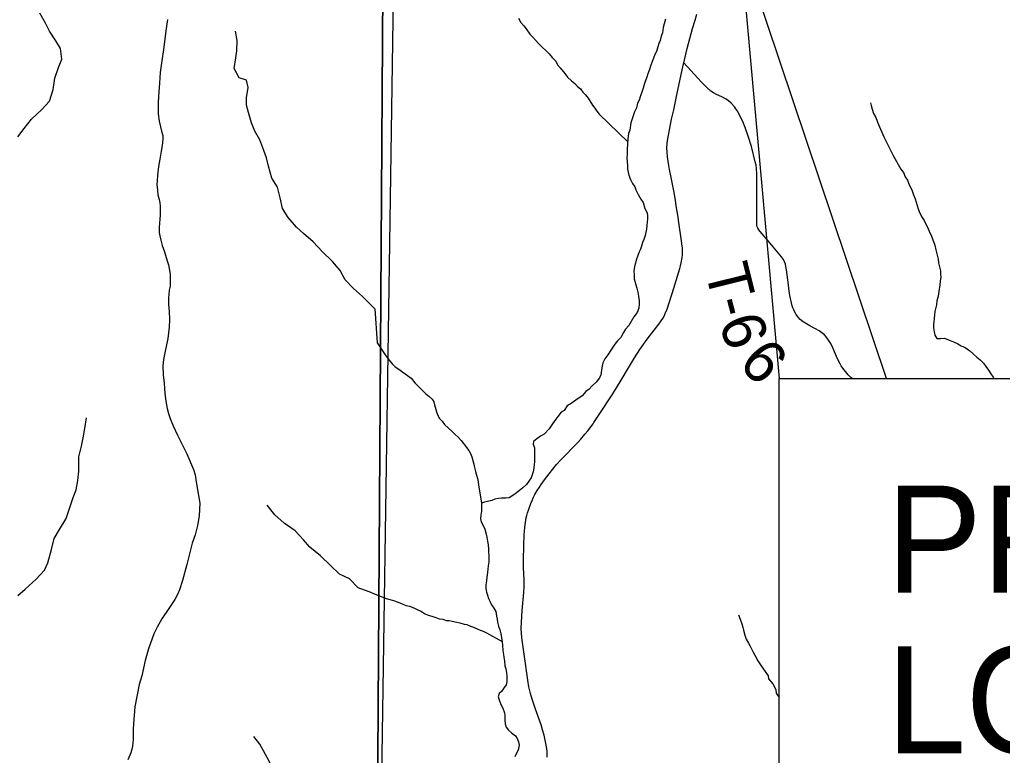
# Model space of a CAD drawing. Extents: x 0 to 34, y 0 to 22.
# Drawn here: x 26.547 to 27.832, y 15.526 to 16.488 of the extents above; entities that cross this region are included whole.
import ezdxf

# ---------------------------------------------------------------- set-up
doc = ezdxf.new("R2010")
doc.units = 0
for name, color, linetype in [('GM_X_Corporation', 7, 'Continuous'), ('GM_X_County', 7, 'Continuous'), ('GM_X_Minor_River', 7, 'Continuous'), ('GM_X_State_Route', 7, 'Continuous'), ('GM_X_Township_Road', 7, 'Continuous'), ('GM_X_Township_Road_Text', 7, 'Continuous'), ('SH_Data', 7, 'Continuous'), ('SH_Text', 7, 'Continuous')]:
    doc.layers.add(name, color=color, linetype=linetype)

msp = doc.modelspace()

# ---------------------------------------------------------------- linework, layer by layer
at = {"layer": 'GM_X_Corporation'}
for points in [[(30.3167, 20.9), (27.1022, 20.9), (27.0898, 20.417), (27.0897, 20.4135), (27.089, 20.3692), (27.0873, 20.2665), (27.0907, 20.123), (27.0885, 20.1139), (27.0864, 20.0138), (27.0761, 19.6806), (27.0733, 19.498), (27.0719, 19.3912), (27.0487, 18.5805), (27.0419, 17.8236), (27.0349, 17.5522), (27.0234, 16.6611), (27.0124, 14.988), (27.0057, 14.5136), (27.2999, 14.5107), (27.8031, 14.5091), (28.4032, 14.497)], [(29.5503, 20.3788), (27.6751, 20.4106), (27.5829, 20.4116), (27.2336, 20.4152), (27.1239, 20.4163), (27.0898, 20.417), (27.0897, 20.4135), (27.089, 20.3692), (27.0873, 20.2665), (27.0907, 20.123), (27.0885, 20.1139), (27.0864, 20.0138), (27.0761, 19.6806), (27.0733, 19.498), (27.0719, 19.3912), (27.0487, 18.5805), (27.0419, 17.8236), (27.0349, 17.5522), (27.0234, 16.6611), (27.0124, 14.988), (27.0057, 14.5136), (27.2999, 14.5107), (27.8031, 14.5091), (28.4032, 14.497)], [(23.5167, 20.3276), (23.5167, 14.5642), (23.7464, 14.562), (24.4108, 14.5557), (24.414, 14.5556), (24.9788, 14.5503), (25.0494, 14.5496), (25.56, 14.5392), (26.009, 14.53), (26.3333, 14.5233), (26.7998, 14.5186), (27.0057, 14.5136), (27.0124, 14.988), (27.0234, 16.6611), (27.0349, 17.5522)], [(23.5167, 20.3276), (23.5167, 14.5642), (23.7464, 14.562), (24.4108, 14.5557), (24.414, 14.5556), (24.9788, 14.5503), (25.0494, 14.5496), (25.56, 14.5392), (26.009, 14.53), (26.3333, 14.5233), (26.7998, 14.5186), (27.0057, 14.5136), (27.0124, 14.988), (27.0234, 16.6611), (27.0349, 17.5522)]]:
    msp.add_lwpolyline(points, dxfattribs=at)
at = {"layer": 'GM_X_County'}
msp.add_line((27.1022, 20.9), (27.0057, 14.5136), dxfattribs=at)
at = {"layer": 'GM_X_Minor_River'}
for points in [[(26.5451, 16.3347), (26.5533, 16.3458), (26.563, 16.3581), (26.5764, 16.3708), (26.5865, 16.3815), (26.5912, 16.3967), (26.5933, 16.4115), (26.5984, 16.4256), (26.6025, 16.4363), (26.6008, 16.4503), (26.5946, 16.4604), (26.5865, 16.4729), (26.5811, 16.4834), (26.5737, 16.4966)], [(27.1999, 16.4901), (27.2026, 16.4845), (27.2065, 16.48), (27.2096, 16.4762), (27.2146, 16.4691), (27.2185, 16.4654), (27.2223, 16.4609), (27.2258, 16.4568), (27.2312, 16.4516), (27.235, 16.4483), (27.24, 16.4434), (27.2439, 16.4386), (27.2485, 16.4337), (27.2509, 16.4292), (27.254, 16.4251), (27.2602, 16.4176), (27.2637, 16.4128), (27.269, 16.4083), (27.2733, 16.4046), (27.2767, 16.4008), (27.2809, 16.3975), (27.284, 16.3934), (27.2875, 16.3897), (27.2906, 16.3856), (27.2965, 16.3762), (27.2995, 16.3724), (27.3023, 16.3683), (27.3054, 16.3646), (27.3425, 16.3285)], [(27.3921, 16.4889), (27.3903, 16.4825), (27.3889, 16.4779), (27.3879, 16.4707), (27.3861, 16.4665), (27.385, 16.4608), (27.3832, 16.4569), (27.3818, 16.4524), (27.38, 16.4463), (27.3778, 16.4424), (27.3764, 16.4379), (27.3745, 16.4333), (27.3724, 16.4272), (27.3709, 16.423), (27.3688, 16.4173), (27.3677, 16.4127), (27.3655, 16.4073), (27.3641, 16.4035), (27.3627, 16.3986), (27.3612, 16.3948), (27.3594, 16.3883), (27.3576, 16.3829), (27.3554, 16.3787), (27.354, 16.373), (27.3515, 16.3677), (27.35, 16.3635), (27.3468, 16.3532), (27.3451, 16.3437), (27.3436, 16.3391), (27.3426, 16.3319), (27.3424, 16.3258), (27.3417, 16.3182), (27.3418, 16.3122), (27.3415, 16.3068), (27.3416, 16.3031), (27.3421, 16.2966), (27.3422, 16.2924), (27.343, 16.2887), (27.3438, 16.2849), (27.3462, 16.2789), (27.3489, 16.274), (27.352, 16.2695), (27.3532, 16.2657), (27.356, 16.2597), (27.3595, 16.2533), (27.3626, 16.2492), (27.365, 16.2413), (27.3678, 16.2353), (27.3682, 16.2315), (27.3683, 16.2277), (27.3677, 16.219), (27.367, 16.214), (27.3652, 16.206), (27.3634, 16.2007), (27.362, 16.1969), (27.3606, 16.1919), (27.3591, 16.1881), (27.3573, 16.1843), (27.3559, 16.1797), (27.3537, 16.1736), (27.3526, 16.1698), (27.3516, 16.1652), (27.3505, 16.1592), (27.351, 16.155), (27.3511, 16.1493), (27.3531, 16.1414), (27.3543, 16.1372), (27.3559, 16.1316), (27.3568, 16.1267)], [(27.0119, 16.1101), (26.9959, 16.1259), (26.984, 16.1367), (26.9729, 16.1479), (26.9667, 16.16), (26.9567, 16.172), (26.9433, 16.1843), (26.9311, 16.1974), (26.9188, 16.2083), (26.9093, 16.2169), (26.8985, 16.2293), (26.8912, 16.2413), (26.888, 16.2553), (26.8844, 16.2689), (26.8771, 16.2809), (26.8727, 16.2964), (26.8703, 16.3074), (26.8668, 16.3172), (26.8613, 16.3311), (26.8548, 16.3424), (26.8505, 16.353), (26.8465, 16.3666), (26.8441, 16.3764), (26.844, 16.3859), (26.8461, 16.3992), (26.8441, 16.409), (26.8346, 16.4119), (26.828, 16.4243), (26.8301, 16.438), (26.8315, 16.4475), (26.8318, 16.4608), (26.8297, 16.4729)], [(27.66, 16.3795), (27.6609, 16.3758), (27.6621, 16.3709), (27.6637, 16.3656), (27.6668, 16.3603), (27.6688, 16.3554), (27.6704, 16.3509), (27.6774, 16.3351), (27.6826, 16.3246), (27.6849, 16.3201), (27.6877, 16.3141), (27.6896, 16.3103), (27.6962, 16.2987), (27.6998, 16.2927), (27.7029, 16.2882), (27.7052, 16.2825), (27.7083, 16.2784), (27.7107, 16.272), (27.7142, 16.2656), (27.7162, 16.2592), (27.7182, 16.2536), (27.7222, 16.2408), (27.7246, 16.2351), (27.7277, 16.2295), (27.7301, 16.2257), (27.732, 16.2216), (27.734, 16.2175), (27.7367, 16.2114), (27.7399, 16.2051), (27.7442, 16.1934), (27.7455, 16.187), (27.7471, 16.1802), (27.7483, 16.1749), (27.7488, 16.1703), (27.7513, 16.1598), (27.7513, 16.1556), (27.7518, 16.1514), (27.7511, 16.1465), (27.7508, 16.1408), (27.7498, 16.1359), (27.7484, 16.1264), (27.7466, 16.1206), (27.7463, 16.1153), (27.7442, 16.1066), (27.7435, 16.102), (27.7432, 16.0975), (27.7426, 16.0929), (27.7423, 16.0891), (27.7423, 16.0853), (27.7432, 16.08), (27.744, 16.0755), (27.7467, 16.0714), (27.7516, 16.0714), (27.7566, 16.0715), (27.7619, 16.0694), (27.7684, 16.0668), (27.7741, 16.0643), (27.7787, 16.0617), (27.7836, 16.0595), (27.7898, 16.0551), (27.7944, 16.0513), (27.799, 16.0469), (27.8032, 16.0432), (27.8075, 16.0391), (27.8109, 16.0346), (27.8144, 16.0297), (27.8172, 16.0252), (27.8203, 16.0207), (27.8212, 16.0188)], [(27.3568, 16.1267), (27.3573, 16.1206), (27.3577, 16.1161), (27.3571, 16.1108), (27.3549, 16.105), (27.3504, 16.0996), (27.3438, 16.0882), (27.3397, 16.0832), (27.3368, 16.0789), (27.3335, 16.0724), (27.329, 16.0682), (27.3257, 16.0636), (27.3213, 16.0571), (27.3165, 16.0498), (27.3124, 16.0444), (27.3102, 16.0394), (27.3088, 16.033), (27.3075, 16.0238), (27.3057, 16.0196), (27.3012, 16.0143), (27.296, 16.0092), (27.2919, 16.005), (27.2878, 16.0019), (27.283, 15.9961), (27.2748, 15.9907), (27.2684, 15.9864), (27.2635, 15.9833), (27.2595, 15.9771), (27.2557, 15.9748), (27.2513, 15.9694), (27.2487, 15.9656), (27.2443, 15.9598), (27.2398, 15.9529), (27.2332, 15.946), (27.2287, 15.9436), (27.2238, 15.9401), (27.2193, 15.9366), (27.219, 15.9328), (27.2206, 15.9283), (27.2208, 15.9147), (27.2205, 15.9101), (27.2202, 15.9063), (27.2199, 15.9018), (27.2189, 15.8968), (27.2163, 15.8892), (27.2134, 15.8846), (27.2101, 15.8804), (27.2052, 15.8757), (27.2011, 15.8726), (27.1952, 15.868), (27.191, 15.8652), (27.1873, 15.8629), (27.1831, 15.8624), (27.1775, 15.8623), (27.1737, 15.8619), (27.1688, 15.8611), (27.165, 15.8595), (27.1594, 15.8579), (27.1552, 15.857), (27.1515, 15.8558), (27.1512, 15.8509), (27.1513, 15.8456), (27.1506, 15.8403), (27.1499, 15.8353), (27.1508, 15.8316), (27.1531, 15.8274), (27.1555, 15.8218), (27.1575, 15.8154), (27.1583, 15.8112), (27.1591, 15.8063), (27.16, 15.8014), (27.1605, 15.7957), (27.1605, 15.7915), (27.161, 15.7878), (27.1611, 15.779), (27.1601, 15.7741), (27.1598, 15.7695), (27.1591, 15.765), (27.1581, 15.7589), (27.1578, 15.7543), (27.1571, 15.749), (27.1572, 15.7441), (27.158, 15.7396), (27.1592, 15.7354), (27.1604, 15.7313), (27.1624, 15.7275), (27.1644, 15.723), (27.1675, 15.7185), (27.1702, 15.7144), (27.1711, 15.7079), (27.1719, 15.7042), (27.1723, 15.7004), (27.1735, 15.6951), (27.1755, 15.6902), (27.1768, 15.6849), (27.1776, 15.68), (27.1784, 15.6747), (27.1789, 15.6702), (27.1794, 15.6634), (27.1802, 15.6581), (27.1807, 15.6543)], [(27.0119, 16.1101), (27.0148, 16.0657), (27.0247, 16.0511), (27.0275, 16.0466), (27.0305, 16.0429), (27.0344, 16.038), (27.0383, 16.0343), (27.0432, 16.0309), (27.0486, 16.0272), (27.0544, 16.0228), (27.0593, 16.0191), (27.064, 16.0131), (27.069, 16.0083), (27.074, 16.0031), (27.0786, 15.999), (27.0824, 15.9956), (27.087, 15.9919), (27.089, 15.9882), (27.0898, 15.9844), (27.0923, 15.9753), (27.0942, 15.9704), (27.0966, 15.9667), (27.0997, 15.9629), (27.1031, 15.9588), (27.1128, 15.9495), (27.117, 15.9458), (27.1208, 15.9421), (27.1247, 15.9376), (27.1278, 15.9339), (27.1317, 15.9286), (27.1348, 15.9249), (27.1371, 15.9208), (27.1387, 15.9166), (27.1411, 15.9068), (27.142, 15.9023), (27.1436, 15.8974), (27.1448, 15.8925), (27.146, 15.8883), (27.1468, 15.8838), (27.1476, 15.88), (27.1515, 15.8558)], [(26.5449, 15.7351), (26.5546, 15.7435), (26.5692, 15.7566), (26.5801, 15.7681), (26.5845, 15.778), (26.5892, 15.7951), (26.5928, 15.8096), (26.5995, 15.8214), (26.6084, 15.8359), (26.6116, 15.8462), (26.6175, 15.8633), (26.6215, 15.8733), (26.6236, 15.8854), (26.625, 15.8976), (26.6248, 15.9165), (26.6284, 15.9306), (26.6305, 15.9412), (26.6326, 15.9534), (26.6347, 15.9674)], [(27.0079, 15.7386), (26.9903, 15.7452), (26.9789, 15.7568), (26.9655, 15.7631), (26.9537, 15.7743), (26.941, 15.7871), (26.9269, 15.7983), (26.9185, 15.808), (26.9077, 15.8196), (26.8932, 15.8297), (26.881, 15.8405), (26.871, 15.8533)], [(27.0079, 15.7386), (27.0265, 15.7312), (27.0314, 15.7301), (27.0375, 15.728), (27.0444, 15.7254), (27.0486, 15.724), (27.0528, 15.7222), (27.0573, 15.7211), (27.063, 15.7189), (27.0672, 15.7167), (27.0722, 15.7146), (27.0775, 15.7112), (27.0817, 15.7094), (27.0863, 15.708), (27.0916, 15.7062), (27.0958, 15.7047), (27.1007, 15.7041), (27.1053, 15.7026), (27.1091, 15.7023), (27.1129, 15.7016), (27.119, 15.7002), (27.1228, 15.6995), (27.1285, 15.6977), (27.1323, 15.697), (27.1368, 15.6952), (27.141, 15.6938), (27.1456, 15.6916), (27.1498, 15.6898), (27.1536, 15.6883), (27.1578, 15.6861), (27.1784, 15.675)], [(27.4874, 15.7097), (27.4897, 15.7041), (27.4917, 15.698), (27.4929, 15.6935), (27.4938, 15.6897), (27.4958, 15.6833), (27.4974, 15.6781), (27.5005, 15.6728), (27.5028, 15.6687), (27.5067, 15.6612), (27.5087, 15.657), (27.5126, 15.6499), (27.5161, 15.6446), (27.5262, 15.63), (27.5267, 15.6263), (27.5324, 15.6195), (27.536, 15.6124), (27.5368, 15.6075), (27.5407, 15.6018)], [(27.1807, 15.6543), (27.1812, 15.6494), (27.182, 15.6433), (27.1832, 15.6392), (27.1841, 15.6346), (27.1845, 15.6293), (27.1843, 15.6221), (27.1836, 15.6183), (27.1803, 15.6137), (27.1781, 15.6099), (27.1743, 15.6068), (27.1733, 15.6026), (27.1745, 15.5985), (27.1768, 15.5928), (27.1792, 15.5876), (27.1816, 15.5819), (27.182, 15.5781), (27.1817, 15.5721), (27.1822, 15.5675), (27.1838, 15.563), (27.1865, 15.5592), (27.1907, 15.5555), (27.1957, 15.5518), (27.198, 15.5481), (27.1996, 15.5439), (27.2008, 15.5394), (27.1991, 15.5329), (27.1969, 15.5291), (27.1951, 15.5241)], [(27.0043, 15.3997), (26.9854, 15.4131), (26.975, 15.4209), (26.9624, 15.4322), (26.949, 15.4434), (26.9376, 15.4557), (26.9254, 15.4601), (26.9124, 15.4679), (26.8983, 15.4795), (26.8914, 15.4896), (26.8806, 15.5032), (26.874, 15.5175), (26.869, 15.5273), (26.8616, 15.5408), (26.8536, 15.5506)]]:
    msp.add_lwpolyline(points, dxfattribs=at)
at = {"layer": 'GM_X_State_Route'}
msp.add_lwpolyline([(27.2374, 15.5237), (27.2372, 15.5309), (27.2367, 15.5351), (27.2359, 15.5394), (27.2349, 15.5437), (27.2331, 15.5523), (27.2312, 15.5596), (27.2293, 15.5658), (27.2277, 15.5708), (27.2221, 15.5867), (27.2174, 15.5997), (27.2153, 15.607), (27.2133, 15.6155), (27.2118, 15.6246), (27.207, 15.6582), (27.2046, 15.6766), (27.2036, 15.6848), (27.2031, 15.6926), (27.2044, 15.7155), (27.2069, 15.739), (27.2073, 15.7471), (27.2072, 15.756), (27.2063, 15.7714), (27.2061, 15.781), (27.2065, 15.8011), (27.2072, 15.8138), (27.2079, 15.8243), (27.2087, 15.8306), (27.2099, 15.8369), (27.2107, 15.8398), (27.2115, 15.8432), (27.2126, 15.8467), (27.2158, 15.8555), (27.2175, 15.8595), (27.2195, 15.8639), (27.2212, 15.8672), (27.2242, 15.8724), (27.2272, 15.877), (27.2294, 15.8801), (27.2338, 15.8862), (27.2398, 15.8943), (27.2495, 15.9065), (27.2552, 15.9127), (27.2768, 15.9348), (27.2811, 15.9395), (27.2866, 15.946), (27.2903, 15.9506), (27.2972, 15.9598), (27.2982, 15.9612), (27.3052, 15.9716), (27.3229, 15.999), (27.3338, 16.0166), (27.3436, 16.0329), (27.3515, 16.0458), (27.3585, 16.0567), (27.3605, 16.0598), (27.368, 16.0702), (27.3831, 16.09), (27.3864, 16.0944), (27.3884, 16.0975), (27.3901, 16.1006), (27.3917, 16.1039), (27.3939, 16.1095), (27.4026, 16.1372), (27.4105, 16.1626), (27.4115, 16.1661), (27.4125, 16.17), (27.4137, 16.1769), (27.414, 16.1806), (27.4142, 16.1851), (27.4141, 16.1897), (27.4139, 16.1921), (27.4125, 16.202), (27.4099, 16.2199), (27.408, 16.2326), (27.4065, 16.2419), (27.4044, 16.2546), (27.4026, 16.2641), (27.3987, 16.284), (27.3972, 16.2923), (27.3963, 16.2975), (27.3945, 16.3089), (27.3939, 16.3149), (27.3938, 16.3205), (27.3941, 16.3262), (27.3945, 16.3303), (27.3975, 16.3461), (27.3999, 16.3578), (27.4006, 16.3613), (27.4026, 16.3702), (27.4068, 16.3899), (27.4151, 16.4286), (27.4159, 16.4318), (27.4203, 16.4503), (27.4274, 16.4765), (27.4305, 16.4876), (27.433, 16.4954)], dxfattribs=at)
at = {"layer": 'GM_X_Township_Road'}
for points in [[(26.7408, 16.4883), (26.7391, 16.4767), (26.7357, 16.4493), (26.7334, 16.4342), (26.7314, 16.4191), (26.7303, 16.4052), (26.7292, 16.3882), (26.7286, 16.3791), (26.7284, 16.3718), (26.7284, 16.3649), (26.7298, 16.3555), (26.7331, 16.3421), (26.7345, 16.3366), (26.7348, 16.3317), (26.734, 16.3237), (26.7326, 16.3161), (26.7308, 16.3058), (26.7292, 16.2959), (26.7278, 16.2847), (26.7272, 16.2771), (26.727, 16.2727), (26.7276, 16.2651), (26.7281, 16.259), (26.7298, 16.2528), (26.7307, 16.2484), (26.7311, 16.2443), (26.7314, 16.2385), (26.7313, 16.2329), (26.7298, 16.2162), (26.7301, 16.21), (26.7307, 16.2056), (26.7319, 16.1998), (26.7339, 16.1929), (26.7367, 16.1845), (26.7405, 16.1726), (26.7421, 16.1673), (26.743, 16.1626), (26.7441, 16.1551), (26.7444, 16.1464), (26.7441, 16.1397), (26.7431, 16.1343), (26.7419, 16.124), (26.7421, 16.1151), (26.7428, 16.1071), (26.7433, 16.0957), (26.7429, 16.0862), (26.7414, 16.0712), (26.7375, 16.0525), (26.7357, 16.0438), (26.7349, 16.0355), (26.7353, 16.0235), (26.7364, 16.0129), (26.7368, 16.0058), (26.7374, 15.9991), (26.7388, 15.9892), (26.7403, 15.9795), (26.742, 15.9732), (26.7444, 15.9667), (26.7483, 15.9571), (26.754, 15.9447), (26.7659, 15.9203), (26.7746, 15.8997), (26.7769, 15.8927), (26.778, 15.8866), (26.7792, 15.8785), (26.783, 15.8557), (26.782, 15.8393), (26.7802, 15.8266), (26.7769, 15.8145), (26.7731, 15.8036), (26.7701, 15.7913), (26.766, 15.7756), (26.7605, 15.7548), (26.7564, 15.7426), (26.7544, 15.7372), (26.7503, 15.7297), (26.7425, 15.7183), (26.7333, 15.7044), (26.7273, 15.6939), (26.7229, 15.6848), (26.7158, 15.6655), (26.7117, 15.6501), (26.7071, 15.6302), (26.7036, 15.6187), (26.6979, 15.5894), (26.6964, 15.5672), (26.696, 15.5605), (26.6959, 15.5467), (26.695, 15.5381), (26.6943, 15.5344), (26.6929, 15.5293), (26.6889, 15.5202)], [(27.6359, 16.0188), (27.6344, 16.0201), (27.6309, 16.0238), (27.6236, 16.0326), (27.6217, 16.0356), (27.6203, 16.038), (27.6169, 16.0448), (27.6142, 16.0506), (27.6108, 16.0591), (27.608, 16.0648), (27.6052, 16.0692), (27.602, 16.0734), (27.5996, 16.076), (27.5965, 16.0786), (27.5927, 16.0812), (27.5881, 16.0839), (27.5808, 16.0878), (27.5761, 16.0905), (27.572, 16.0931), (27.568, 16.0961), (27.5648, 16.0993), (27.5626, 16.1026), (27.5609, 16.1057), (27.5595, 16.1086), (27.5584, 16.1113), (27.5577, 16.1139), (27.5567, 16.1178), (27.5545, 16.1276), (27.5536, 16.1334), (27.5531, 16.1366), (27.5526, 16.1414), (27.5512, 16.1545), (27.5503, 16.1609), (27.5494, 16.1655), (27.5486, 16.1682), (27.5476, 16.1713), (27.5462, 16.1743), (27.5436, 16.1781), (27.5371, 16.186), (27.526, 16.1987), (27.5156, 16.2109), (27.5138, 16.2134), (27.5127, 16.2154), (27.5119, 16.217), (27.5115, 16.2191), (27.5113, 16.2218), (27.5112, 16.2247), (27.5113, 16.2722), (27.5112, 16.2864), (27.5109, 16.2937), (27.5103, 16.2977), (27.5093, 16.3024), (27.5043, 16.3223), (27.5006, 16.3346), (27.4961, 16.347), (27.4929, 16.3548), (27.4901, 16.3606), (27.4863, 16.368), (27.484, 16.3717), (27.4825, 16.3738), (27.4779, 16.3789), (27.4742, 16.3821), (27.4712, 16.3843), (27.4654, 16.3873), (27.4584, 16.3903), (27.4545, 16.3924), (27.4513, 16.3945), (27.4461, 16.3992), (27.439, 16.4064), (27.434, 16.4118), (27.4159, 16.4318)]]:
    msp.add_lwpolyline(points, dxfattribs=at)
at = {"layer": 'SH_Data'}
for points in [[(27.5407, 16.0188), (27.6807, 16.0188), (27.4891, 16.5897)], [(27.5407, 16.0188), (28.8122, 16.0188), (28.8122, 15.3888), (27.5407, 15.3888)]]:
    msp.add_lwpolyline(points, close=True, dxfattribs=at)

# ---------------------------------------------------------------- texts
at = {"layer": 'GM_X_Township_Road_Text'}
for s, rotation, p in [('T', 283.9411, (27.443, 16.1618)), ('-', 284.5926, (27.4534, 16.1198)), ('6', 289.5294, (27.4608, 16.0922)), ('6', 313.1419, (27.4857, 16.0375))]:
    msp.add_text(s, height=0.0568, rotation=rotation, dxfattribs=at).set_placement(p)
at = {"layer": 'SH_Text'}
for s, p in [('PROJECT', (27.6807, 15.7388)), ('LOCATION', (27.6807, 15.5288))]:
    msp.add_text(s, height=0.14, dxfattribs=at).set_placement(p)

doc.saveas('drawing.dxf')
